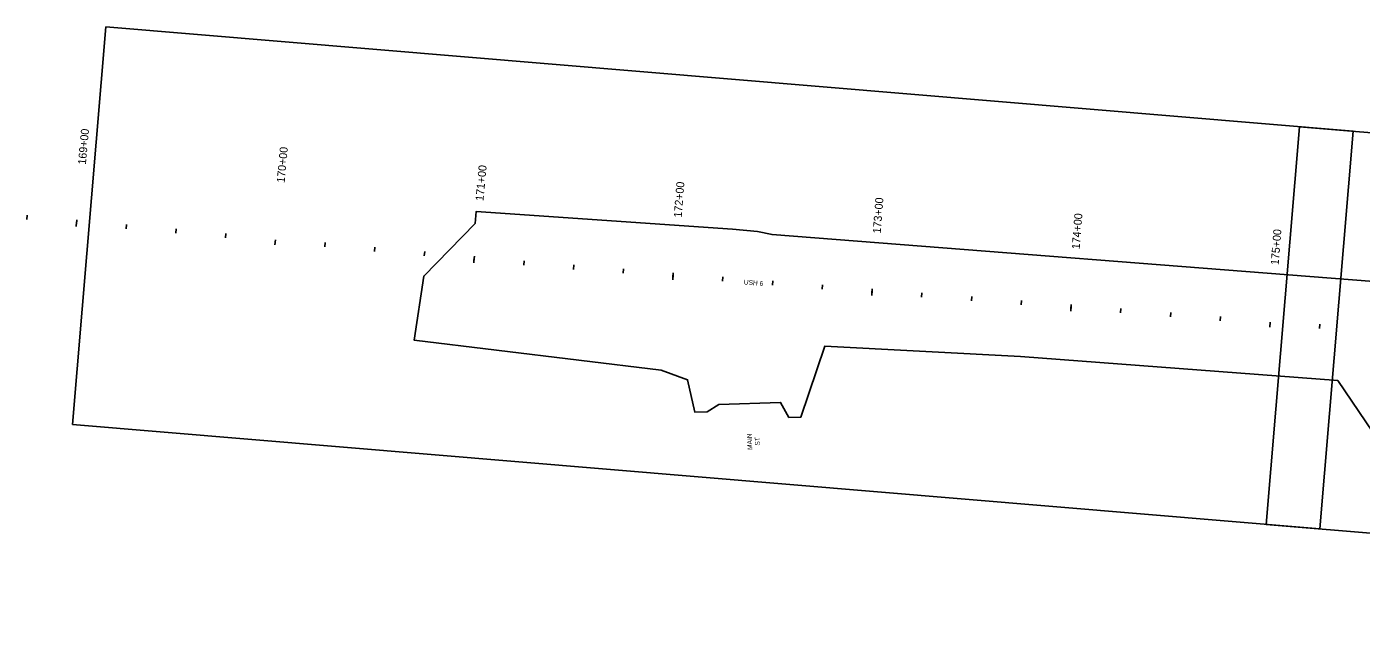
# Model space of a CAD drawing. Extents: x 20499876 to 20505320, y 7953544 to 7954108.
# Drawn here: x 20500588 to 20501256, y 7953788 to 7954090 of the extents above; entities that cross this region are included whole.
import ezdxf

# ---------------------------------------------------------------- set-up
doc = ezdxf.new("R2010")
doc.units = 0
for name, color, linetype in [('Alignment', 7, 'Continuous'), ('Curb', 7, 'Continuous'), ('Draft_0', 7, 'Continuous'), ('Draft_7', 7, 'Continuous'), ('UtilitiesBelowGround', 7, 'Continuous')]:
    doc.layers.add(name, color=color, linetype=linetype)

msp = doc.modelspace()

# ---------------------------------------------------------------- linework, layer by layer
at = {"layer": 'Alignment'}
for points in [[(20500627.39, 7954089.64), (20500610.68, 7953890.34), (20501235.48, 7953837.95), (20501252.19, 7954037.25)], [(20501225.23, 7954039.5), (20501208.63, 7953840.19), (20501833.46, 7953788.16), (20501850.06, 7953987.47)]]:
    msp.add_lwpolyline(points, close=True, dxfattribs=at)
at = {"layer": 'Curb'}
for p, q in [((20500612.57, 7953990.69), (20500612.77, 7953992.86)), ((20500712.27, 7953982.79), (20500712.04, 7953980.35)), ((20500811.74, 7953972.46), (20500811.94, 7953974.64)), ((20500911.39, 7953964.08), (20500911.56, 7953966.26)), ((20501011.07, 7953956.16), (20501011.24, 7953958.33)), ((20501110.76, 7953948.24), (20501110.93, 7953950.41)), ((20501210.54, 7953941.53), (20501210.35, 7953939.09))]:
    msp.add_line(p, q, dxfattribs=at)
at = {"layer": 'Draft_7'}
for p, q in [((20500587.68, 7953992.96), (20500587.87, 7953995.14)), ((20500612.68, 7953991.91), (20500612.46, 7953989.47)), ((20500637.47, 7953988.41), (20500637.67, 7953990.58)), ((20500662.36, 7953986.13), (20500662.56, 7953988.3)), ((20500687.26, 7953983.85), (20500687.46, 7953986.03)), ((20500712.27, 7953982.79), (20500712.04, 7953980.35)), ((20500737.05, 7953979.29), (20500737.25, 7953981.47)), ((20500761.95, 7953977.02), (20500762.15, 7953979.19)), ((20500786.84, 7953974.74), (20500787.04, 7953976.91)), ((20500811.85, 7953973.68), (20500811.63, 7953971.24)), ((20500836.64, 7953970.18), (20500836.83, 7953972.36)), ((20500861.54, 7953968.04), (20500861.72, 7953970.22)), ((20500886.46, 7953966.06), (20500886.64, 7953968.24)), ((20500911.48, 7953965.3), (20500911.29, 7953962.86)), ((20500936.31, 7953962.1), (20500936.48, 7953964.28)), ((20500961.23, 7953960.12), (20500961.4, 7953962.3)), ((20500986.15, 7953958.14), (20500986.32, 7953960.31)), ((20501011.17, 7953957.38), (20501010.97, 7953954.94)), ((20501035.99, 7953954.18), (20501036.17, 7953956.35)), ((20501060.91, 7953952.2), (20501061.09, 7953954.37)), ((20501085.84, 7953950.22), (20501086.01, 7953952.39)), ((20501110.85, 7953949.46), (20501110.66, 7953947.02)), ((20501135.68, 7953946.26), (20501135.85, 7953948.43)), ((20501160.6, 7953944.27), (20501160.77, 7953946.45)), ((20501185.52, 7953942.29), (20501185.69, 7953944.47)), ((20501210.54, 7953941.53), (20501210.35, 7953939.09)), ((20501235.36, 7953938.33), (20501235.54, 7953940.51))]:
    msp.add_line(p, q, dxfattribs=at)
at = {"layer": 'UtilitiesBelowGround'}
msp.add_lwpolyline([(20501261.93, 7953886.46), (20501244.4, 7953912.4), (20501085.46, 7953924.44), (20500987.46, 7953929.51), (20500975.54, 7953894.02), (20500969.49, 7953893.86), (20500965.3, 7953901.35), (20500934.39, 7953900.27), (20500928.56, 7953896.65), (20500922.42, 7953896.4), (20500918.72, 7953912.73), (20500905.46, 7953917.46), (20500781.85, 7953932.48), (20500786.55, 7953964.7), (20500812.3, 7953991.06), (20500812.66, 7953994.97), (20500812.81, 7953996.95), (20500941.31, 7953988.1), (20500953.71, 7953986.99), (20500961.05, 7953985.49), (20501585.27, 7953936.81)], dxfattribs=at)

# ---------------------------------------------------------------- texts
at = {"layer": 'Curb'}
for s, rotation, p in [('170+00', 84.77145, (20500716.88, 7954011.27)), ('175+00', 85.45642, (20501214.82, 7953970.06))]:
    msp.add_text(s, height=4.008, rotation=rotation, dxfattribs=at).set_placement(p)
at = {"layer": 'Draft_0'}
for s, rotation, p in [('USH 6', 355, (20500946.82, 7953960.52)), ('MAIN', 91.87706, (20500951.17, 7953877.58)), ('ST', 91.87706, (20500954.94, 7953879.75))]:
    msp.add_text(s, height=2.4, rotation=rotation, dxfattribs=at).set_placement(p)
at = {"layer": 'Draft_7'}
for s, rotation, p in [('169+00', 84.77145, (20500617.3, 7954020.38)), ('170+00', 84.77145, (20500716.88, 7954011.27)), ('171+00', 84.77145, (20500816.47, 7954002.15)), ('172+00', 85.45642, (20500915.76, 7953993.83)), ('173+00', 85.45642, (20501015.45, 7953985.9)), ('174+00', 85.45642, (20501115.13, 7953977.98)), ('175+00', 85.45642, (20501214.82, 7953970.06))]:
    msp.add_text(s, height=4.008, rotation=rotation, dxfattribs=at).set_placement(p)

doc.saveas('drawing.dxf')
